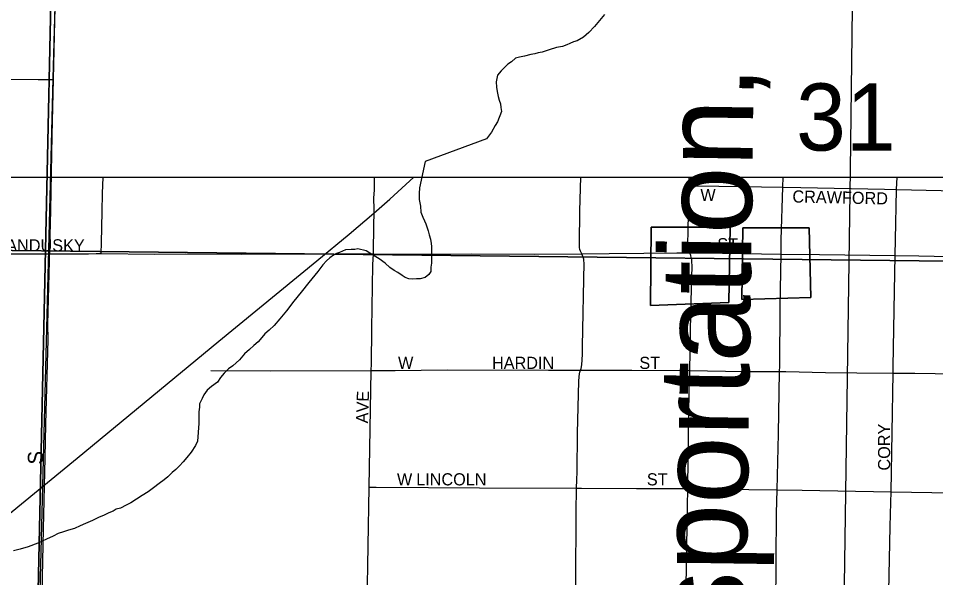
# Model space of a CAD drawing. Extents: x 0 to 68, y 0 to 52.9.
# Drawn here: x 43.122 to 43.878, y 38.205 to 38.666 of the extents above; entities that cross this region are included whole.
import ezdxf

# ---------------------------------------------------------------- set-up
doc = ezdxf.new("R2010")
doc.units = 0
for name, color, linetype in [('Default', 7, 'Continuous'), ('GM_X_County_Road', 7, 'Continuous'), ('GM_X_Minor_Lake', 7, 'Continuous'), ('GM_X_Minor_River', 7, 'Continuous'), ('GM_X_Township', 7, 'Continuous'), ('GM_X_Township_Road', 7, 'Continuous')]:
    doc.layers.add(name, color=color, linetype=linetype)

msp = doc.modelspace()

# ---------------------------------------------------------------- linework, layer by layer
at = {"layer": 'Default'}
msp.add_line((42.25806, 38.53508), (49.65006, 38.53508), dxfattribs=at)
for points in [[(41.82896, 39.29088), (43.1609, 39.26536), (43.13273, 37.95279), (41.80876, 37.97561)], [(43.1609, 39.26536), (44.47349, 39.25009), (44.45233, 37.93902), (44.41032, 37.93957), (43.13273, 37.95279)], [(42.87499, 38.47751), (43.93627, 38.46518), (43.9204, 37.41034), (42.85875, 37.42389)]]:
    msp.add_lwpolyline(points, close=True, dxfattribs=at)
for points in [[(43.15051, 38.61542), (43.15158, 38.66375), (43.15566, 38.82641)], [(43.64162, 32.7683), (43.64334, 34.0176), (43.64455, 34.6783), (43.65599, 35.34849), (43.66788, 36.0083), (43.67702, 36.44587), (43.68602, 36.84543), (43.69035, 37.04683), (43.69592, 37.28989), (43.69757, 37.31546), (43.70235, 37.35703), (43.70606, 37.38349), (43.71865, 37.45038), (43.791, 37.87267), (43.79415, 37.89545), (43.79589, 37.91564), (43.79763, 37.93547), (43.7985, 37.95966), (43.79937, 37.99098), (43.80146, 38.12323), (43.80732, 38.54108), (43.80967, 38.71924)], [(43.14239, 38.24528), (43.14357, 38.30385), (43.14417, 38.33164), (43.14615, 38.40135), (43.14603, 38.41367), (43.14825, 38.50793), (43.1495, 38.56946), (43.15051, 38.61542)], [(42.25806, 37.5546), (42.66184, 37.88702), (43.17003, 38.30369), (43.28687, 38.4), (43.36751, 38.46624), (43.39418, 38.48818), (43.4146, 38.50525), (43.4277, 38.51683), (43.44096, 38.52887), (43.44755, 38.53508)], [(43.93775, 38.53508), (43.93627, 38.46518), (42.87499, 38.47751), (42.87603, 38.53508)], [(43.18999, 38.47209), (43.19014, 38.48104), (43.19058, 38.50679), (43.19103, 38.52155), (43.19143, 38.53508)], [(43.41422, 38.47176), (43.4142, 38.47587), (43.41485, 38.50874), (43.41462, 38.51779), (43.41501, 38.52465), (43.41522, 38.53508)], [(43.58586, 38.4718), (43.58497, 38.47407), (43.58444, 38.47559), (43.58415, 38.47705), (43.58395, 38.48006), (43.5844, 38.50722), (43.58502, 38.53508)], [(43.67436, 38.528), (43.6745, 38.53508)], [(43.75172, 38.52684), (43.75203, 38.53508)], [(43.84537, 38.52491), (43.84573, 38.53508)], [(43.67506, 38.47274), (43.67442, 38.47436), (43.67403, 38.47539), (43.67385, 38.47593), (43.6737, 38.47652), (43.67359, 38.47715), (43.67353, 38.47768), (43.67346, 38.47835), (43.67355, 38.49224), (43.67436, 38.528)], [(43.67436, 38.528), (43.68124, 38.5279), (43.75172, 38.52684)], [(43.75014, 38.47175), (43.7503, 38.4835), (43.75172, 38.52684)], [(43.75172, 38.52684), (43.76644, 38.52661), (43.8355, 38.52509), (43.84537, 38.52491)], [(43.84411, 38.47042), (43.84462, 38.49706), (43.84498, 38.51081), (43.84537, 38.52491)], [(43.84537, 38.52491), (43.9313, 38.52298), (43.94146, 38.52275)], [(43.04064, 38.47178), (43.06083, 38.47149), (43.07531, 38.47167), (43.08453, 38.4718), (43.13022, 38.47193), (43.17942, 38.472), (43.1857, 38.47214), (43.18999, 38.47209)], [(43.18999, 38.47209), (43.23398, 38.47159), (43.25967, 38.47199), (43.30558, 38.47173), (43.38388, 38.47184), (43.41422, 38.47176)], [(43.4124, 38.37585), (43.41251, 38.38118), (43.41285, 38.41022), (43.41382, 38.46274), (43.41422, 38.47176)], [(43.41422, 38.47176), (43.43961, 38.47173), (43.49512, 38.47186), (43.54737, 38.47172), (43.58586, 38.4718)], [(43.58495, 38.37595), (43.58546, 38.37757), (43.5859, 38.38049), (43.58639, 38.38902), (43.58655, 38.39564), (43.58787, 38.46466), (43.58775, 38.46587), (43.58765, 38.46671), (43.58749, 38.4676), (43.58697, 38.46921), (43.58586, 38.4718)], [(43.58586, 38.4718), (43.60838, 38.47211), (43.63694, 38.47243), (43.66432, 38.47264), (43.67506, 38.47274)], [(43.6751, 38.37573), (43.67571, 38.42302), (43.67682, 38.46205), (43.67671, 38.46537), (43.67653, 38.46703), (43.67633, 38.46826), (43.67619, 38.46896), (43.67579, 38.47047), (43.67506, 38.47274)], [(43.67506, 38.47274), (43.68746, 38.4726), (43.70186, 38.47256), (43.75014, 38.47175)], [(43.74897, 38.37501), (43.74907, 38.3794), (43.74945, 38.42788), (43.75014, 38.47175)], [(43.75014, 38.47175), (43.78189, 38.47121), (43.84411, 38.47042)], [(43.84249, 38.37365), (43.84258, 38.37871), (43.84359, 38.44118), (43.84411, 38.47042)], [(43.84411, 38.47042), (43.86371, 38.47017), (43.9401, 38.46868)], [(43.28017, 38.37569), (43.32926, 38.37545), (43.4124, 38.37585)], [(43.41081, 38.27968), (43.4124, 38.37585)], [(43.4124, 38.37585), (43.4321, 38.37582), (43.47511, 38.37628), (43.5584, 38.3761), (43.58495, 38.37595)], [(43.58168, 38.27883), (43.58199, 38.28585), (43.58217, 38.29233), (43.58234, 38.3243), (43.58349, 38.36689), (43.58378, 38.37055), (43.58411, 38.37301), (43.58438, 38.37434), (43.58495, 38.37595)], [(43.58495, 38.37595), (43.60873, 38.37601), (43.62726, 38.37602), (43.6751, 38.37573)], [(43.67332, 38.27852), (43.67348, 38.30356), (43.67455, 38.35846), (43.6751, 38.37573)], [(43.6751, 38.37573), (43.71904, 38.37507), (43.74897, 38.37501)], [(43.74697, 38.27753), (43.7481, 38.32365), (43.74897, 38.37501)], [(43.74897, 38.37501), (43.75422, 38.37499), (43.78684, 38.37427), (43.81254, 38.374), (43.84249, 38.37365)], [(43.84082, 38.27585), (43.84249, 38.37365)], [(43.84249, 38.37365), (43.86053, 38.37349), (43.9103, 38.37267), (43.93324, 38.37222), (43.9388, 38.37218)], [(43.40919, 38.18305), (43.41081, 38.27968)], [(43.41081, 38.27968), (43.4166, 38.27966), (43.4597, 38.2795), (43.50154, 38.27906), (43.58168, 38.27883)], [(43.57869, 38.18188), (43.57951, 38.18337), (43.58021, 38.18463), (43.58049, 38.18586), (43.58065, 38.18752), (43.58109, 38.20082), (43.58122, 38.25908), (43.58168, 38.27883)], [(43.58168, 38.27883), (43.5858, 38.27884), (43.63107, 38.27862), (43.67332, 38.27852)], [(43.67164, 38.18167), (43.67319, 38.26371), (43.67332, 38.27852)], [(43.67332, 38.27852), (43.67685, 38.27848), (43.74697, 38.27753)], [(43.74576, 38.18028), (43.7465, 38.25844), (43.74697, 38.27753)], [(43.74697, 38.27753), (43.7675, 38.27728), (43.84082, 38.27585)], [(43.83881, 38.17917), (43.8391, 38.19389), (43.84014, 38.24738), (43.8407, 38.26698), (43.84082, 38.27585)], [(43.84082, 38.27585), (43.89117, 38.27503), (43.93727, 38.27455)]]:
    msp.add_lwpolyline(points, dxfattribs=at)
at = {"layer": 'GM_X_County_Road'}
msp.add_lwpolyline([(43.14133, 38.19231), (43.14239, 38.24528)], dxfattribs=at)
at = {"layer": 'GM_X_Minor_Lake'}
for points in [[(43.64302, 38.49381), (43.7082, 38.49384), (43.70721, 38.4317), (43.64257, 38.42927), (43.64302, 38.49381)], [(43.64302, 38.49381), (43.64257, 38.42927), (43.70721, 38.4317)], [(43.70721, 38.4317), (43.7082, 38.49384), (43.64302, 38.49381)], [(43.71856, 38.49329), (43.77338, 38.49336), (43.77478, 38.43594), (43.71794, 38.43427), (43.71856, 38.49329)], [(43.77478, 38.43594), (43.77338, 38.49336), (43.71856, 38.49329)], [(43.71856, 38.49329), (43.71794, 38.43427), (43.77478, 38.43594)]]:
    msp.add_lwpolyline(points, dxfattribs=at)
at = {"layer": 'GM_X_Minor_River'}
for points in [[(43.60468, 38.66903), (43.60057, 38.6641), (43.59645, 38.65917), (43.59184, 38.65425), (43.58724, 38.65033), (43.58217, 38.64742), (43.57914, 38.64648), (43.5761, 38.64504), (43.57357, 38.64408), (43.57003, 38.64265), (43.565, 38.64175), (43.55894, 38.63987), (43.55338, 38.63797), (43.54986, 38.63754), (43.54733, 38.63659), (43.54381, 38.63616), (43.53877, 38.63475), (43.53473, 38.63383), (43.53121, 38.6329), (43.52814, 38.62995), (43.52509, 38.62801), (43.52202, 38.62506), (43.51946, 38.62261), (43.51638, 38.61916), (43.51527, 38.61366), (43.51568, 38.60914), (43.5161, 38.60562), (43.51703, 38.60159), (43.51797, 38.59857), (43.51891, 38.59554), (43.51935, 38.59252), (43.51978, 38.589), (43.5166, 38.58054), (43.51453, 38.57757), (43.51141, 38.57212), (43.50729, 38.56668), (43.45673, 38.548)], [(43.45673, 38.548), (43.45209, 38.52619), (43.45205, 38.52167), (43.452, 38.51665), (43.45295, 38.51111), (43.4534, 38.50609), (43.45487, 38.50205), (43.45635, 38.49902), (43.45733, 38.4965), (43.45928, 38.49095), (43.46025, 38.48743), (43.46122, 38.4839), (43.46169, 38.48038), (43.46217, 38.47786), (43.46213, 38.47384), (43.4621, 38.47133), (43.46207, 38.46782), (43.46203, 38.4643), (43.4615, 38.46079), (43.46147, 38.45727), (43.45993, 38.45478), (43.45689, 38.4523), (43.45287, 38.45133), (43.44985, 38.45136), (43.44633, 38.4509), (43.44332, 38.45143), (43.44032, 38.45247), (43.43782, 38.454), (43.43433, 38.45655), (43.43133, 38.45809), (43.42783, 38.46064), (43.42385, 38.46419), (43.41886, 38.46776), (43.41486, 38.47031), (43.41137, 38.47236), (43.40837, 38.4744), (43.40135, 38.47598), (43.39884, 38.47551), (43.39583, 38.47554), (43.3913, 38.47508), (43.38878, 38.4741), (43.38626, 38.47312), (43.38373, 38.47214), (43.3812, 38.47066), (43.37817, 38.46868), (43.37564, 38.4662), (43.37259, 38.46271), (43.36851, 38.45723), (43.36089, 38.44827), (43.35478, 38.44029), (43.34868, 38.43282), (43.34257, 38.42485), (43.33698, 38.41837), (43.3324, 38.4129), (43.32835, 38.40892), (43.3248, 38.40594), (43.32226, 38.40295), (43.31921, 38.39947), (43.31566, 38.39649), (43.31211, 38.39301), (43.30806, 38.38954), (43.30399, 38.38456), (43.29842, 38.37959), (43.29487, 38.37712), (43.29132, 38.37364), (43.28828, 38.37015), (43.28572, 38.36616), (43.28066, 38.3627), (43.27712, 38.35972), (43.27457, 38.35572), (43.27303, 38.35273), (43.27097, 38.34823), (43.27095, 38.34572), (43.27041, 38.3417), (43.27037, 38.33718), (43.27032, 38.33216), (43.26917, 38.3176), (43.26763, 38.3141), (43.26406, 38.30861), (43.26049, 38.30413), (43.25745, 38.30064), (43.2544, 38.29716), (43.25135, 38.29418), (43.24831, 38.2917), (43.24476, 38.28821), (43.24172, 38.28573), (43.23768, 38.28276), (43.23312, 38.27929), (43.22856, 38.27582), (43.22351, 38.27286), (43.21896, 38.26989), (43.21441, 38.26693), (43.21037, 38.26496), (43.20582, 38.2625), (43.2023, 38.26153), (43.19977, 38.26005), (43.19624, 38.25858), (43.1922, 38.25661)], [(43.1922, 38.25661), (43.18766, 38.25465), (43.18261, 38.25219), (43.17706, 38.24973), (43.17252, 38.24777), (43.16798, 38.24581), (43.16294, 38.24435), (43.1589, 38.24289), (43.15437, 38.24143), (43.15033, 38.23946), (43.14478, 38.23701), (43.13771, 38.23356), (43.12964, 38.23063), (43.12309, 38.22869), (43.11755, 38.22724)]]:
    msp.add_lwpolyline(points, dxfattribs=at)
at = {"layer": 'GM_X_Township'}
msp.add_lwpolyline([(50.34506, 37.77433), (49.87003, 37.78728), (49.7424, 37.78907), (49.09193, 37.81286), (48.42924, 37.83782), (47.97584, 37.8521), (47.09341, 37.87493), (46.43542, 37.88698), (45.78152, 37.90751), (45.76356, 37.9078), (44.77759, 37.93161), (44.12143, 37.94309), (43.3203, 37.94792), (43.31455, 37.9477), (43.13228, 37.95106), (43.13722, 38.12535), (43.1394, 38.18651), (43.13947, 38.19396), (43.15039, 38.61621), (43.15805, 38.89613)], dxfattribs=at)
at = {"layer": 'GM_X_Township_Road'}
msp.add_lwpolyline([(43.06496, 38.61601), (43.13784, 38.61551), (43.15051, 38.61542)], dxfattribs=at)

# ---------------------------------------------------------------- texts
at = {"layer": 'Default'}
for s, height, rotation, p in [('Transportation,', 0.07475, 89.17029, (43.71802, 37.95448)), ('31', 0.05525, 0.00001, (43.7625, 38.55695)), ('W', 0.01, 0.00001, (43.68365, 38.51542)), ('CRAWFORD', 0.01, 358.71162, (43.75943, 38.51423)), ('SANDUSKY', 0.01, 0.00001, (43.10274, 38.4739)), ('ST', 0.01, 0.00001, (43.69762, 38.47478)), ('W', 0.01, 0.00001, (43.4345, 38.3771)), ('HARDIN', 0.01, 0.00001, (43.51194, 38.3771)), ('ST', 0.01, 0.00001, (43.63338, 38.3771)), ('AVE', 0.01, 88.02609, (43.40974, 38.33216)), ('CORY', 0.01, 90, (43.84006, 38.29338)), ('S', 0.0125, 90, (43.14195, 38.29838)), ('W', 0.01, 0.00001, (43.43362, 38.28118)), ('LINCOLN', 0.01, 0.00001, (43.44946, 38.28118)), ('ST', 0.01, 0.00001, (43.63954, 38.28118))]:
    msp.add_text(s, height=height, rotation=rotation, dxfattribs=at).set_placement(p)

doc.saveas('drawing.dxf')
